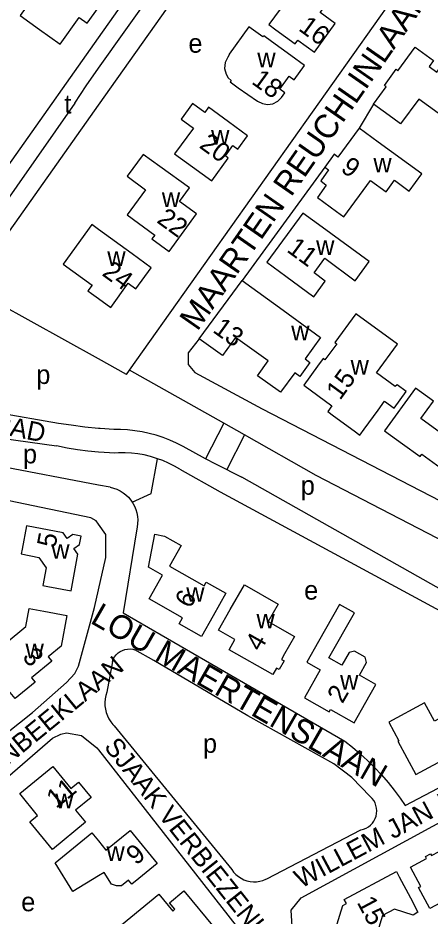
# Model space of a CAD drawing. Extents: x 156721 to 158827, y 386657 to 388950.
# Drawn here: x 158033 to 158120, y 387292.3 to 387481.8 of the extents above; entities that cross this region are included whole.
import ezdxf

# ---------------------------------------------------------------- set-up
doc = ezdxf.new("R2010")
doc.units = 0
for name, color, linetype in [('BLT_Basislijn', 7, 'Continuous'), ('BLT_Bebouwing', 7, 'Continuous'), ('BLT_Centroide', 7, 'Continuous'), ('BLT_Huisnummer', 7, 'Continuous'), ('BLT_Straatnaam', 7, 'Continuous'), ('BLT_Straatnaam_verkleind', 7, 'Continuous')]:
    doc.layers.add(name, color=color, linetype=linetype)

msp = doc.modelspace()

# ---------------------------------------------------------------- linework, layer by layer
at = {"layer": 'BLT_Basislijn'}
for p, q in [((158056.58, 387407.52), (158122.17, 387500)), ((158045, 387463.84), (158018.61, 387426.15)), ((158022.81, 387424.96), (158050, 387463.38)), ((158108.05, 387463.61), (158104.98, 387458.56)), ((158097.74, 387450.31), (158080.31, 387426.43)), ((158050, 387409.87), (158022.81, 387424.96)), ((158055.91, 387406.59), (158050, 387409.87)), ((158055.91, 387406.59), (158056.58, 387407.52)), ((158076.47, 387396.28), (158056.58, 387407.52)), ((158041.59, 387396.27), (158009.54, 387401.71)), ((158076.47, 387396.28), (158072.61, 387388.81)), ((158080.83, 387393.82), (158076.47, 387396.28)), ((158080.83, 387393.82), (158077.06, 387386.53)), ((158050, 387383.25), (158003.22, 387392.22)), ((158072.61, 387388.81), (158067.86, 387391.41)), ((158073.54, 387388.3), (158072.61, 387388.81)), ((158073.54, 387388.3), (158077.06, 387386.53)), ((158067.19, 387386.59), (158075.71, 387381.86)), ((158122.89, 387360.87), (158080.24, 387384.91)), ((158052.44, 387382.78), (158050, 387383.25)), ((158052.93, 387346.02), (158051.79, 387339.53)), ((158053.32, 387332.47), (158078.12, 387302.12)), ((157998.81, 387294.14), (158040.29, 387329.84)), ((158040.29, 387329.84), (158042.05, 387330.67)), ((158042.05, 387330.67), (158043.26, 387331.02)), ((158043.26, 387331.02), (158046.44, 387330.43)), ((158046.44, 387330.43), (158049.65, 387327.83)), ((158049.65, 387327.83), (158050, 387327.38)), ((158085.56, 387300.21), (158105.39, 387310.52))]:
    msp.add_line(p, q, dxfattribs=at)
for points in [[(158050, 387477.59), (158066.22, 387500.55), (158077.29, 387518.68), (158071.97, 387526.92), (158073.91, 387528.5)], [(158050, 387471.2), (158073.06, 387503.66), (158082.38, 387519.34), (158082.08, 387521.98), (158081.33, 387523.57), (158080.15, 387524.61), (158073.91, 387528.5)], [(158050, 387463.38), (158083.07, 387510.1), (158087.92, 387519.56), (158087.89, 387522.31)], [(158015.22, 387428.35), (158050, 387477.59)], [(158045, 387463.84), (158047.38, 387467.51), (158050, 387471.2)], [(158071.27, 387414.1), (158068.9, 387411.18), (158068.9, 387408.72), (158070.31, 387407.03), (158084.55, 387399.32), (158126.29, 387377.77), (158127.56, 387377.58)], [(158002.23, 387398.69), (158029.57, 387393.17), (158041.17, 387391.51)], [(158050, 387395.21), (158047.12, 387395.49), (158044.24, 387395.86), (158041.59, 387396.27)], [(158053.22, 387394.98), (158050.33, 387395.18), (158050, 387395.21)], [(158067.86, 387391.41), (158066.49, 387392.11), (158065.09, 387392.73), (158063.65, 387393.29), (158062.19, 387393.76), (158060.71, 387394.16), (158059.21, 387394.48), (158057.69, 387394.73), (158056.16, 387394.89), (158054.63, 387394.98), (158053.22, 387394.98)], [(158143.03, 387360.87), (158095.94, 387385.29), (158080.83, 387393.82)], [(158050, 387390.19), (158047.78, 387390.4), (158045.58, 387390.69), (158043.38, 387391.05), (158041.17, 387391.51)], [(158053.46, 387390.02), (158051.23, 387390.11), (158050, 387390.19)], [(158062.47, 387388.82), (158062.28, 387388.89), (158060.98, 387389.28), (158059.66, 387389.6), (158058.32, 387389.83), (158056.97, 387389.99), (158055.62, 387390.06), (158054.26, 387390.06), (158053.46, 387390.02)], [(158057.13, 387379.68), (158061.14, 387381.48), (158062.47, 387388.82)], [(158067.19, 387386.59), (158066.02, 387387.27), (158064.81, 387387.88), (158063.56, 387388.43), (158062.47, 387388.82)], [(158077.06, 387386.53), (158078.02, 387386.05), (158080.24, 387384.91)], [(158050, 387375.02), (158049.49, 387375.73), (158048.37, 387376.34), (158031.13, 387379.93), (158003.61, 387384.4), (157998.01, 387384.1), (157955.51, 387349.64), (157954.23, 387347.08), (157954.56, 387344.01), (157955.96, 387341.99), (157966.08, 387329.93), (157977.64, 387316.81), (157988.08, 387303.39), (157990.8, 387302.06), (157994.9, 387302.57), (158036.09, 387335.26), (158043.26, 387341.61), (158045.02, 387343.53), (158045.82, 387345.07), (158049.16, 387357.46), (158050, 387361.12)], [(158052.44, 387382.78), (158053.17, 387382.61), (158053.88, 387382.36), (158054.56, 387382.04), (158055.21, 387381.65), (158055.81, 387381.19), (158056.35, 387380.67), (158056.84, 387380.1), (158057.13, 387379.68)], [(158075.71, 387381.86), (158122.89, 387356.3), (158156.35, 387342.67)], [(158057.13, 387379.68), (158057.27, 387379.47), (158057.62, 387378.81), (158057.91, 387378.11), (158058.12, 387377.38), (158058.25, 387376.64), (158058.3, 387375.89), (158058.27, 387375.14), (158058.16, 387374.39), (158058.09, 387374.04)], [(158050, 387361.12), (158051.57, 387367.97), (158051.57, 387372.86), (158050, 387375.02)], [(158058.09, 387374.04), (158055.22, 387356.33), (158101.96, 387329.23)], [(158052.93, 387346.02), (158053.13, 387346.54), (158053.4, 387347.01), (158053.74, 387347.45), (158054.13, 387347.83), (158054.58, 387348.14), (158055.07, 387348.39), (158055.59, 387348.57), (158056.13, 387348.67), (158056.68, 387348.69), (158057.22, 387348.63), (158057.7, 387348.51)], [(158107.3, 387317.58), (158103.49, 387321.59), (158099.67, 387324.45), (158081.55, 387334.57), (158061.71, 387346.22), (158057.7, 387348.51)], [(158051.79, 387339.53), (158051.57, 387338.84), (158051.42, 387338.13), (158051.35, 387337.41), (158051.37, 387336.68), (158051.46, 387335.97), (158051.63, 387335.26), (158051.88, 387334.58), (158052.2, 387333.93), (158052.59, 387333.32), (158053.05, 387332.75), (158053.32, 387332.47)], [(158114.74, 387315.67), (158139.73, 387328.84), (158150.99, 387334.95)], [(158202.47, 387311.95), (158214.91, 387307.07), (158215.87, 387306.53), (158217.72, 387304.61), (158217.99, 387303.33), (158217.94, 387300.68), (158214.72, 387292.99), (158213.57, 387292.13), (158145.07, 387255.37), (158142.51, 387255.42), (158135.67, 387258.85), (158105.8, 387276.82), (158097.93, 387282.39), (158090.84, 387290.13), (158090.68, 387293.59), (158092.76, 387296.21), (158148.33, 387326.39), (158153.68, 387328.54), (158155.35, 387328.95), (158159.41, 387328.66), (158161.42, 387327.99), (158202.47, 387311.95)], [(158101.96, 387329.23), (158103.62, 387327.93), (158105.22, 387326.57), (158106.78, 387325.15), (158108.27, 387323.67), (158109.72, 387322.13), (158111.1, 387320.54), (158112.42, 387318.9), (158113.68, 387317.22), (158114.74, 387315.67)], [(158050, 387327.38), (158087.17, 387279.93), (158095.06, 387273.16), (158102.83, 387268.88), (158104.9, 387266.35), (158105.06, 387263.42), (158104.45, 387262.03), (158095.71, 387250)], [(158105.39, 387310.52), (158105.95, 387310.66), (158106.47, 387310.87), (158106.96, 387311.15), (158107.41, 387311.51), (158107.8, 387311.92), (158108.13, 387312.38), (158108.4, 387312.88), (158108.59, 387313.42), (158108.7, 387313.97), (158108.73, 387314.54), (158108.69, 387315.11), (158108.56, 387315.66), (158108.36, 387316.19), (158108.09, 387316.69), (158107.74, 387317.14), (158107.3, 387317.58)], [(158078.12, 387302.12), (158078.52, 387301.58), (158078.99, 387301.09), (158079.52, 387300.66), (158080.09, 387300.29), (158080.7, 387300), (158081.34, 387299.78), (158082.01, 387299.63), (158082.68, 387299.57), (158083.36, 387299.58), (158084.03, 387299.67), (158084.69, 387299.85), (158085.32, 387300.09), (158085.56, 387300.21)]]:
    msp.add_lwpolyline(points, dxfattribs=at)
at = {"layer": 'BLT_Bebouwing'}
msp.add_line((158071.27, 387414.1), (158080.31, 387426.43), dxfattribs=at)
for points in [[(158050, 387488.85), (158047.59, 387490.58), (158043.54, 387493.48), (158041.5, 387490.64), (158040.81, 387491.13), (158038.34, 387487.67), (158037.65, 387488.17), (158033.46, 387482.3), (158037.53, 387479.4), (158041.93, 387476.26), (158045.9, 387481.89), (158047.61, 387480.68), (158050, 387484.04)], [(158095.74, 387489.94), (158094.14, 387491.1), (158091.19, 387487.08), (158090.95, 387487.26), (158085.94, 387480.4), (158087.45, 387479.29), (158091.48, 387476.33), (158092.07, 387477.14), (158095.55, 387474.59), (158099.98, 387480.65), (158096.79, 387482.97), (158099.78, 387486.99), (158095.74, 387489.94)], [(158077.78, 387468.31), (158079.47, 387467.09), (158083.56, 387464.25), (158084.58, 387463.73), (158085.7, 387463.54), (158086.79, 387463.71), (158087.83, 387464.24), (158088.62, 387465.05), (158089.3, 387466.01), (158088.27, 387466.76), (158090.26, 387469.53), (158091.28, 387468.77), (158093.45, 387471.8), (158090.57, 387473.89), (158086.52, 387476.84), (158084.87, 387478.04), (158084.69, 387477.8), (158081.73, 387479.9), (158077.6, 387474.19)], [(158108.05, 387463.61), (158110.7, 387467.25), (158110.32, 387467.54), (158112.8, 387471), (158113.2, 387470.68), (158116.85, 387475.65), (158120.71, 387472.82), (158119.76, 387471.53), (158121.38, 387470.35), (158122.33, 387471.64), (158132.98, 387463.81)], [(158077.6, 387474.19), (158077.68, 387474.14), (158077.29, 387473.56), (158076.73, 387472.42), (158076.61, 387471.13), (158076.92, 387469.97), (158077.38, 387469.19), (158077.98, 387468.59), (158077.78, 387468.31)], [(158132.98, 387463.81), (158130.03, 387459.77), (158126.78, 387455.33), (158123.21, 387457.93), (158124.46, 387459.65), (158117.59, 387464.67), (158113.74, 387459.43), (158112.08, 387460.65), (158108.05, 387463.61)], [(158077.44, 387459.89), (158073.24, 387462.97), (158072.45, 387461.89), (158069.86, 387463.76), (158067.45, 387460.44), (158070.02, 387458.57), (158066.07, 387453.14), (158069.85, 387450.39), (158073.89, 387447.45), (158077.4, 387452.24), (158076.79, 387452.71), (158078.36, 387454.89), (158079.4, 387454.13), (158081.47, 387456.93), (158077.44, 387459.89)], [(158097.74, 387450.31), (158098.55, 387449.73), (158096.89, 387447.44), (158098.08, 387446.55), (158096.21, 387443.95), (158100.24, 387440.99), (158101.78, 387439.86), (158107.38, 387447.54), (158110.68, 387445.14), (158112.43, 387447.55), (158115.55, 387445.27), (158118.22, 387448.95), (158109.02, 387455.62), (158104.98, 387458.56)], [(158104.98, 387458.56), (158100.52, 387452.41), (158099.73, 387453.04), (158097.74, 387450.31)], [(158062.98, 387450.44), (158059.44, 387453.02), (158056.08, 387448.41), (158059.96, 387445.57), (158056.07, 387440.25), (158061.88, 387435.99), (158061.29, 387435.18), (158064.91, 387432.53), (158070.67, 387440.48), (158067.12, 387443.09), (158069.21, 387445.94), (158062.98, 387450.44)], [(158097.17, 387437.68), (158093.14, 387440.63), (158085.52, 387430.26), (158089.55, 387427.3), (158095.43, 387422.98), (158097.86, 387426.28), (158095.48, 387428.03), (158097.75, 387431.1), (158104.18, 387426.36), (158107.14, 387430.39), (158097.17, 387437.68)], [(158050, 387437.2), (158048.61, 387438.21), (158042.57, 387429.86), (158048.65, 387425.46), (158047.77, 387424.24), (158048.55, 387423.68), (158050, 387422.63)], [(158050, 387422.63), (158052.6, 387420.75), (158056.29, 387425.85), (158057.9, 387424.64), (158061.14, 387429.11), (158057.09, 387432.05), (158050, 387437.2)], [(158080.31, 387426.43), (158088.94, 387420.16), (158096.87, 387414.37), (158093.59, 387409.87), (158094.62, 387409.11), (158092.49, 387406.18), (158091.44, 387406.94), (158088.44, 387402.83), (158083.57, 387406.32), (158085.83, 387409.47), (158078.92, 387414.42), (158076.17, 387410.59), (158071.27, 387414.1)], [(158108.99, 387399.06), (158110.35, 387400.93), (158112.38, 387399.46), (158114.95, 387402.98), (158113.02, 387404.39), (158112.63, 387404.05), (158108.68, 387406.93), (158113.1, 387413), (158104.28, 387419.41), (158099.87, 387413.35), (158100.27, 387413.05), (158097.8, 387409.66), (158097.4, 387409.95), (158096.25, 387408.37), (158093.31, 387404.33), (158099.23, 387399.98), (158098.37, 387398.75), (158099.59, 387397.87), (158103.95, 387394.68), (158105.17, 387393.81), (158106.04, 387395.02), (158108.99, 387399.06)], [(158122.97, 387393.68), (158118.01, 387397.29), (158120.68, 387400.98), (158116.89, 387403.73), (158110.35, 387394.73), (158114.14, 387391.97), (158117.88, 387389.25), (158118.26, 387389.78), (158122.87, 387386.43)], [(158039.3, 387361.89), (158044.21, 387360.95), (158045.66, 387368.67), (158044.83, 387369.88), (158046.02, 387370.72), (158046.38, 387372.49), (158044.6, 387372.8), (158043.39, 387371.96), (158042.53, 387373.19), (158034.84, 387374.67), (158033.91, 387369.76), (158033.71, 387368.72), (158037.43, 387368.01), (158038.97, 387365.81), (158038.26, 387362.09), (158039.3, 387361.89)], [(158074.19, 387355.66), (158071.72, 387351.31), (158067, 387353.98), (158067.75, 387355.28), (158060.7, 387359.28), (158063.52, 387364.24), (158060.59, 387365.92), (158061.89, 387372.9), (158063.91, 387372.51), (158067.45, 387370.49), (158065, 387366.16), (158072.28, 387362.02), (158072.72, 387362.79), (158076.89, 387360.43), (158074.19, 387355.66)], [(158089.28, 387347.64), (158088.61, 387346.46), (158089.17, 387346.14), (158088.15, 387344.36), (158087.59, 387344.65), (158086.8, 387343.3), (158077.57, 387348.52), (158078.8, 387350.7), (158075.34, 387352.66), (158077.81, 387357.01), (158080.79, 387362.23), (158087.91, 387358.16), (158085.8, 387354.46), (158091.35, 387351.3), (158089.28, 387347.64)], [(158106.4, 387337.46), (158108.51, 387341.18), (158105.05, 387343.14), (158106.59, 387345.84), (158106.43, 387346.39), (158106.28, 387346.94), (158104.03, 387348.23), (158103.47, 387348.08), (158102.92, 387347.92), (158101.38, 387345.23), (158098.62, 387346.81), (158104.02, 387356.29), (158100.89, 387358.08), (158096.43, 387350.26), (158093.96, 387345.92), (158096.8, 387344.29), (158093.45, 387338.35), (158098.68, 387335.41), (158098.97, 387335.93), (158103.94, 387333.11), (158106.4, 387337.46)], [(158038.45, 387356.67), (158043.36, 387355.74), (158042.14, 387349.29), (158039.39, 387347.03), (158040.15, 387346.11), (158035.89, 387342.62), (158036.65, 387341.69), (158032.42, 387338.2), (158029.24, 387342.06), (158025.86, 387346.16), (158034.66, 387353.41), (158035.41, 387357.25), (158038.45, 387356.67)], [(158130.41, 387335.07), (158128.93, 387337.78), (158120.92, 387333.42), (158118.83, 387337.29), (158111.27, 387333.22), (158113.36, 387329.32), (158113.16, 387329.2), (158116.95, 387322.16), (158132.8, 387330.67), (158130.41, 387335.07)], [(158040.37, 387323.87), (158044.16, 387319.26), (158045.77, 387320.58), (158048.43, 387317.33), (158045.17, 387314.67), (158047.26, 387312.11), (158040.28, 387306.4), (158035.52, 387312.22), (158037.15, 387313.53), (158033.39, 387318.18), (158040.37, 387323.87)], [(158050, 387308.2), (158051.57, 387306.26), (158056.7, 387310.41), (158062.4, 387303.45), (158058.55, 387300.26), (158057.06, 387299.03), (158056.33, 387299.91), (158054.87, 387298.71), (158053.8, 387298.71), (158052.78, 387299.03), (158051.17, 387301.5), (158050, 387300.8)], [(158134.26, 387288.16), (158130.27, 387295.53), (158128.3, 387294.47), (158127.78, 387295.43), (158126.99, 387295), (158124.72, 387295.46), (158124.3, 387296.25), (158119.89, 387293.93), (158117.53, 387298.33), (158118.02, 387298.59), (158115.82, 387302.68), (158119.21, 387304.5), (158119.01, 387304.88), (158120.09, 387305.46), (158120.28, 387305.08), (158121.89, 387305.92), (158123.29, 387305.47), (158125.44, 387306.63), (158124.66, 387308.04), (158129.4, 387310.57), (158131.77, 387306.17)], [(158050, 387300.8), (158044.6, 387297.53), (158040.86, 387303.53), (158044.76, 387306.73), (158048.62, 387309.9), (158050, 387308.2)], [(158100.02, 387289.6), (158101.54, 387294.55), (158102.31, 387294.97), (158101.85, 387295.84), (158112.86, 387301.73), (158113.46, 387300.59), (158115.81, 387296.17), (158117.42, 387293.12), (158116.41, 387292.54), (158112.44, 387293.81), (158109.96, 387292.48), (158108.13, 387286.45)], [(158068.02, 387297.62), (158074.39, 387289.9), (158073.85, 387289.46), (158076.02, 387286.83), (158069.42, 387281.37), (158063.18, 387288.91), (158057.79, 387284.46), (158053.64, 387289.48), (158054.87, 387290.49), (158062.71, 387296.96), (158062.71, 387296.95), (158065.68, 387293.35), (158066.15, 387293.75), (158065.02, 387295.12), (158068.02, 387297.62)]]:
    msp.add_lwpolyline(points, dxfattribs=at)

# ---------------------------------------------------------------- texts
at = {"layer": 'BLT_Centroide'}
for s, p in [('e', (158068.98, 387474.47)), ('w', (158083.52, 387471.39)), ('t', (158042.8, 387461.64)), ('w', (158073.77, 387455.06)), ('w', (158108.01, 387449.22)), ('w', (158063.38, 387441.91)), ('w', (158095.93, 387431.81)), ('w', (158051.87, 387429.47)), ('w', (158090.67, 387413.81)), ('w', (158103.2, 387406.58)), ('p', (158036.88, 387404.58)), ('p', (158034.07, 387387.83)), ('p', (158092.69, 387381.21)), ('w', (158040.05, 387367.7)), ('w', (158068.52, 387358.64)), ('e', (158093.4, 387359.09)), ('w', (158083.34, 387353)), ('w', (158034.61, 387346.69)), ('w', (158100.98, 387340.12)), ('p', (158072.05, 387326.76)), ('w', (158040.91, 387315.06)), ('w', (158051.68, 387303.97)), ('e', (158033.7, 387293.34))]:
    msp.add_text(s, height=4, dxfattribs=at).set_placement(p)
at = {"layer": 'BLT_Huisnummer'}
for s, rotation, p in [('16', 324.0147, (158092.01, 387479.31)), ('18', 324.0147, (158082.11, 387468.08)), ('20', 324.0147, (158071.07, 387454.57)), ('9', 323.7283, (158100.9, 387449.61)), ('22', 324.0147, (158062.1, 387438.79)), ('11', 323.7128, (158089.53, 387432.62)), ('24', 324.0147, (158050.56, 387427.62)), ('13', 324.3213, (158073.92, 387415.65)), ('15', 53.9229, (158100.97, 387400.99)), ('5', 79.2677, (158040.9, 387369.88)), ('6', 60.4257, (158069.36, 387357.04)), ('4', 60.4055, (158084.21, 387347.96)), ('3', 309.5063, (158033.78, 387346.9)), ('2', 60.4669, (158101.5, 387336.99)), ('11', 39.2827, (158041.08, 387314.89)), ('9', 39.5869, (158057.93, 387302.92)), ('15', 298.1456, (158104.44, 387295.24))]:
    msp.add_text(s, height=4, rotation=rotation, dxfattribs=at).set_placement(p)
at = {"layer": 'BLT_Straatnaam'}
for s, rotation, p in [('MAARTEN REUCHLINLAAN', 55.1091, (158070.88, 387415.55)), ('LOU MAERTENSLAAN', 330.1751, (158048.06, 387354.27))]:
    msp.add_text(s, height=5, rotation=rotation, dxfattribs=at).set_placement(p)
at = {"layer": 'BLT_Straatnaam_verkleind'}
for s, rotation, p in [('RIEN VAN BRUGGENPAD', 348.864, (157974.82, 387404.74)), ('BERNARD SCHOONBEEKLAAN', 39.3498, (157994.32, 387294.1)), ('WILLEM JAN JONKERLAAN', 28.1766, (158092.73, 387298.09)), ('SJAAK VERBIEZENLAAN', 308.3498, (158051.02, 387327.99))]:
    msp.add_text(s, height=4, rotation=rotation, dxfattribs=at).set_placement(p)

doc.saveas('drawing.dxf')
